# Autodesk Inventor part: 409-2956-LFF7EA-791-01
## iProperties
Shininess: 64.0
Angle Display Precision: 2
Document Length Units: 11272
Document Angle Units: 11279
Document Time Units: 11290
Document Mass Units: 11286
Document Length Units Precision: 3
Document Angle Units Precision: 2
Compacted: True
Created: 2002-04
Part Number: 409-2956-LFF7EA-791-01
Description: DISCHARGE PIPE STAND ANGLE
Document SubType Name: Modeling
Designer: S. Boerckel
Mass: 4384.85 g
Surface Area: 1829.27 cm^2
Volume: 558.58 cm^3
Density: 7.85 g/cm^3
Cost Center: 2 x 2 x 1/4 ANGLE
Material: ASTM A36
Engineer: S. Boerckel
Density: 0.0
Volumn: 0.0
Area: 0.0
PropertySet Name: Model Information
Control State: 0
Master: False
Checked Out: False
length: 36.440 in
SMR: =<COST CENTER> - <MATERIAL>
Author: S. Boerckel
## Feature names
1. Extrusion1
